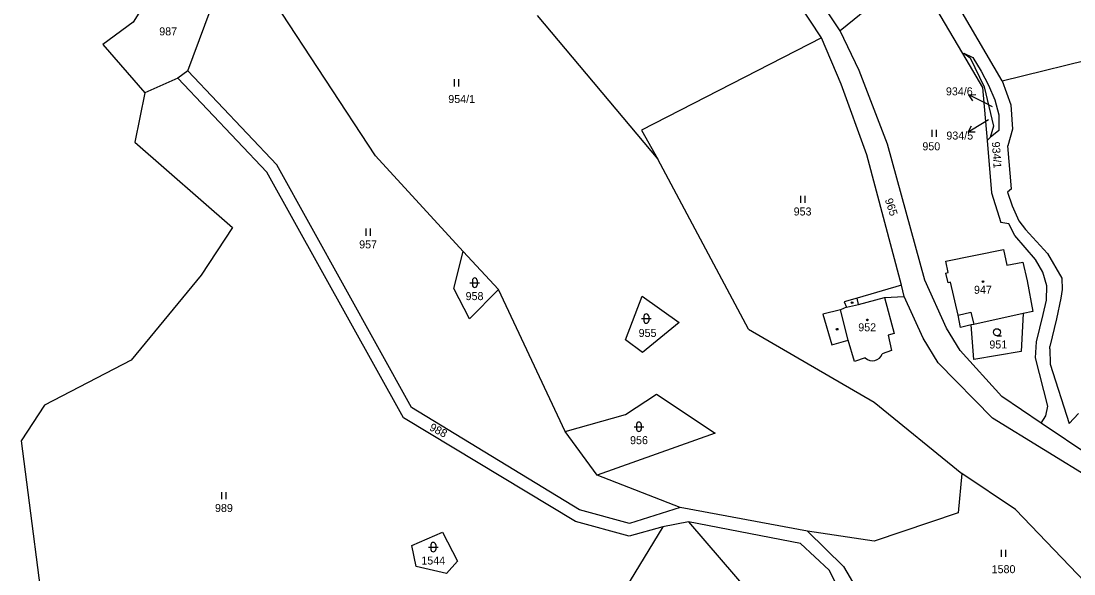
# Model space of a CAD drawing. Extents: x -670359 to -668019, y -978807 to -976674.
# Drawn here: x -669572.2 to -669348.5, y -977907.6 to -977790.2 of the extents above; entities that cross this region are included whole.
import ezdxf

# ---------------------------------------------------------------- set-up
doc = ezdxf.new("R2010")
doc.units = 0
for name, color, linetype in [('Hranice parcel', 7, 'Continuous'), ('Parcelní čísla', 7, 'Continuous'), ('Vnitřní kresba', 7, 'Continuous'), ('Značky budov', 7, 'Continuous'), ('Značky kultur', 7, 'Continuous')]:
    doc.layers.add(name, color=color, linetype=linetype)

msp = doc.modelspace()

# ---------------------------------------------------------------- linework, layer by layer
at = {"layer": 'Hranice parcel'}
for points in [[(-669496.86, -977818.78), (-669528.95, -977769.91)], [(-669398.16, -977792.22), (-669412.75, -977770.41)], [(-669402.15, -977793.77), (-669417.31, -977770.76)], [(-669363.72, -977802.89), (-669379.05, -977776.69)], [(-669540.35, -977777.57), (-669548.36, -977790.4)], [(-669382.48, -977779.5), (-669398.16, -977792.22)], [(-669382.48, -977779.5), (-669372.18, -977797.06)], [(-669536.76, -977800.75), (-669529.53, -977781.26)], [(-669548.36, -977790.4), (-669554.81, -977795.16)], [(-669462.55, -977789.01), (-669436.91, -977819.49)], [(-669394.12, -977800.67), (-669398.16, -977792.22)], [(-669554.81, -977795.16), (-669545.86, -977805.45)], [(-669402.15, -977793.77), (-669440.35, -977813.33)], [(-669397.94, -977803.57), (-669402.15, -977793.77)], [(-669372.18, -977797.06), (-669371.87, -977797.01)], [(-669372.18, -977797.06), (-669367.95, -977804.27)], [(-669371.87, -977797.01), (-669370.56, -977798)], [(-669371.87, -977797.01), (-669369.99, -977797.91)], [(-669370.56, -977798), (-669367.54, -977804.12)], [(-669369.99, -977797.91), (-669368.18, -977800.82)], [(-669536.76, -977800.75), (-669538.86, -977802.32)], [(-669517.84, -977820.71), (-669536.76, -977800.75)], [(-669388.11, -977816.3), (-669394.12, -977800.67)], [(-669368.18, -977800.82), (-669366.63, -977803.8)], [(-669538.86, -977802.32), (-669545.86, -977805.45)], [(-669519.94, -977822.28), (-669538.86, -977802.32)], [(-669392.5, -977818.56), (-669397.94, -977803.57)], [(-669367.54, -977804.12), (-669365.6, -977812.48)], [(-669366.63, -977803.8), (-669365.29, -977806.88)], [(-669363.72, -977802.89), (-669361.92, -977807.97)], [(-669545.86, -977805.45), (-669547.97, -977815.9)], [(-669367.95, -977804.27), (-669366.96, -977815.51)], [(-669365.29, -977806.88), (-669364.43, -977810.08)], [(-669361.92, -977807.97), (-669361.56, -977813.16)], [(-669364.43, -977810.08), (-669364.43, -977813.41)], [(-669365.6, -977812.48), (-669366.28, -977814.88)], [(-669440.35, -977813.33), (-669436.91, -977819.49)], [(-669366.28, -977814.88), (-669366.96, -977815.51)], [(-669364.43, -977813.41), (-669366.28, -977814.88)], [(-669361.56, -977813.16), (-669362.54, -977816.65)], [(-669547.97, -977815.9), (-669527.27, -977834.04)], [(-669380.2, -977845.18), (-669388.11, -977816.3)], [(-669366.96, -977815.51), (-669365.99, -977826.63)], [(-669361.75, -977825.81), (-669362.54, -977816.65)], [(-669478.28, -977839.13), (-669496.86, -977818.78)], [(-669417.65, -977855.63), (-669436.91, -977819.49)], [(-669385.15, -977846.25), (-669392.5, -977818.56)], [(-669489.25, -977872.21), (-669517.84, -977820.71)], [(-669490.95, -977874.43), (-669519.94, -977822.28)], [(-669361.75, -977825.81), (-669362.63, -977826.48)], [(-669362.63, -977826.48), (-669361.65, -977829.42)], [(-669365.99, -977826.63), (-669364.06, -977832.93)], [(-669361.65, -977829.42), (-669360.19, -977832.63)], [(-669362.31, -977833.23), (-669364.06, -977832.93)], [(-669361.02, -977835.69), (-669362.31, -977833.23)], [(-669360.19, -977832.63), (-669358.81, -977834.45)], [(-669527.27, -977834.04), (-669533.94, -977844.13)], [(-669358.81, -977834.45), (-669354.11, -977839.55)], [(-669356.64, -977840.83), (-669361.02, -977835.69)], [(-669480.23, -977846.97), (-669478.28, -977839.13)], [(-669470.72, -977847.16), (-669478.28, -977839.13)], [(-669373.12, -977852.63), (-669374.71, -977845.65), (-669375.18, -977845.76), (-669375.68, -977843.68), (-669375.18, -977843.57), (-669375.73, -977841.18), (-669363.45, -977838.66), (-669362.78, -977842.01), (-669359.38, -977841.34)], [(-669354.11, -977839.55), (-669351.08, -977844.76)], [(-669359.38, -977841.34), (-669358.45, -977845.37)], [(-669355.13, -977843.5), (-669356.64, -977840.83)], [(-669533.94, -977844.13), (-669548.78, -977862.2)], [(-669354.22, -977846.4), (-669355.13, -977843.5)], [(-669385.15, -977846.25), (-669394.58, -977849.02)], [(-669384.58, -977848.64), (-669385.15, -977846.25)], [(-669375.59, -977855.38), (-669380.2, -977845.18)], [(-669358.45, -977845.37), (-669357.26, -977851.85)], [(-669354.33, -977849.44), (-669354.22, -977846.4)], [(-669351.08, -977844.76), (-669351.03, -977847.19)], [(-669476.92, -977853.43), (-669480.23, -977846.97)], [(-669470.72, -977847.16), (-669476.92, -977853.43)], [(-669456.56, -977877.36), (-669470.72, -977847.16)], [(-669443.79, -977857.86), (-669440.24, -977848.57)], [(-669440.24, -977848.57), (-669432.37, -977854.2)], [(-669388.74, -977848.91), (-669384.58, -977848.64)], [(-669388.74, -977848.91), (-669386.7, -977856.49)], [(-669380.53, -977857.49), (-669384.58, -977848.64)], [(-669351.03, -977847.19), (-669351.29, -977849.05)], [(-669396.8, -977850.95), (-669398.08, -977851.52)], [(-669394.58, -977849.02), (-669397.29, -977849.76)], [(-669397.29, -977849.76), (-669396.8, -977850.95)], [(-669355, -977852.45), (-669354.33, -977849.44)], [(-669351.29, -977849.05), (-669352.17, -977853.37)], [(-669398.08, -977851.52), (-669401.83, -977852.42)], [(-669401.83, -977852.42), (-669399.96, -977858.96)], [(-669372.6, -977855.26), (-669373.12, -977852.63)], [(-669359.3, -977852.3), (-669369.79, -977854.59)], [(-669359.3, -977852.3), (-669359.73, -977860.32)], [(-669357.26, -977851.85), (-669359.3, -977852.3)], [(-669356.46, -977858.3), (-669355, -977852.45)], [(-669352.17, -977853.37), (-669353.65, -977859.3)], [(-669432.37, -977854.2), (-669440.18, -977860.56)], [(-669417.65, -977855.63), (-669390.94, -977871.13)], [(-669372.68, -977860.16), (-669375.59, -977855.38)], [(-669370.31, -977854.71), (-669372.6, -977855.26)], [(-669369.79, -977854.59), (-669370.31, -977854.71)], [(-669369.79, -977862.06), (-669370.31, -977854.71)], [(-669440.18, -977860.56), (-669443.79, -977857.86)], [(-669386.7, -977856.49), (-669387.98, -977856.89)], [(-669387.98, -977856.89), (-669387.24, -977860.16)], [(-669377.31, -977862.74), (-669380.53, -977857.49)], [(-669399.96, -977858.96), (-669396.45, -977857.9)], [(-669395.14, -977862.45), (-669396.45, -977857.9)], [(-669356.68, -977861.66), (-669356.46, -977858.3)], [(-669353.65, -977859.8), (-669353.65, -977859.3)], [(-669353.65, -977859.8), (-669353.58, -977863.01)], [(-669548.78, -977862.2), (-669567.21, -977871.76)], [(-669392.83, -977861.72), (-669395.14, -977862.45)], [(-669387.24, -977860.16), (-669389.23, -977860.82)], [(-669363.83, -977869.93), (-669372.68, -977860.16)], [(-669359.73, -977860.32), (-669369.79, -977862.06)], [(-669354.06, -977871.95), (-669356.68, -977861.66)], [(-669365.81, -977874.5), (-669377.31, -977862.74)], [(-669353.58, -977863.01), (-669349.49, -977875.6)], [(-669443.78, -977873.69), (-669437.17, -977869.41)], [(-669437.17, -977869.41), (-669424.73, -977877.65)], [(-669390.94, -977871.13), (-669372.28, -977886.27)], [(-669355.46, -977875.53), (-669363.83, -977869.93)], [(-669567.21, -977871.76), (-669572.17, -977879.31)], [(-669453.53, -977893.95), (-669489.25, -977872.21)], [(-669354.44, -977874.02), (-669354.06, -977871.95)], [(-669349.49, -977875.6), (-669347.5, -977873.51)], [(-669454.36, -977896.42), (-669490.95, -977874.43)], [(-669456.56, -977877.36), (-669443.78, -977873.69)], [(-669344.14, -977887.8), (-669365.81, -977874.5)], [(-669355.46, -977875.53), (-669354.44, -977874.02)], [(-669344.89, -977882.61), (-669355.46, -977875.53)], [(-669449.79, -977886.59), (-669456.56, -977877.36)], [(-669424.73, -977877.65), (-669449.79, -977886.59)], [(-669572.17, -977879.31), (-669566.4, -977923.76)], [(-669432.16, -977893.46), (-669449.79, -977886.59)], [(-669372.28, -977886.27), (-669373.09, -977894.58)], [(-669360.92, -977893.91), (-669372.28, -977886.27)], [(-669432.16, -977893.46), (-669442.92, -977896.86)], [(-669405.07, -977898.47), (-669432.16, -977893.46)], [(-669442.92, -977896.86), (-669453.53, -977893.95)], [(-669373.09, -977894.58), (-669390.93, -977900.62)], [(-669360.92, -977893.91), (-669341.2, -977914.44)], [(-669442.95, -977899.58), (-669454.36, -977896.42)], [(-669435.8, -977897.58), (-669451.69, -977923.64)], [(-669435.8, -977897.58), (-669442.95, -977899.58)], [(-669430.35, -977896.52), (-669435.8, -977897.58)], [(-669406.62, -977901.09), (-669430.35, -977896.52)], [(-669430.35, -977896.52), (-669416.9, -977912.18)], [(-669489.16, -977901.56), (-669482.64, -977898.67)], [(-669482.64, -977898.67), (-669479.42, -977904.86)], [(-669390.93, -977900.62), (-669405.07, -977898.47)], [(-669405.07, -977898.47), (-669397.47, -977905.99)], [(-669488.24, -977905.97), (-669489.16, -977901.56)], [(-669400.52, -977906.76), (-669406.62, -977901.09)], [(-669479.42, -977904.86), (-669481.77, -977907.48)], [(-669481.77, -977907.48), (-669488.24, -977905.97)], [(-669394.16, -977918.98), (-669400.52, -977906.76)], [(-669397.47, -977905.99), (-669391.02, -977916.94)]]:
    msp.add_lwpolyline(points, dxfattribs=at)
msp.add_arc((-669391.32, -977860.12), 2.2, 226.5107, 341.5618, dxfattribs=at)
at = {"layer": 'Parcelní čísla'}
for p, q in [((-669370.01, -977807.09), (-669370.83, -977805.84)), ((-669365.77, -977808.39), (-669367.26, -977807.64)), ((-669366.64, -977811.15), (-669367.56, -977811.71)), ((-669369.48, -977813.75), (-669370.98, -977813.78))]:
    msp.add_line(p, q, dxfattribs=at)
for points in [[(-669367.26, -977807.64), (-669370.83, -977805.84), (-669369.33, -977805.75)], [(-669367.56, -977811.71), (-669370.98, -977813.78), (-669370.26, -977812.46)]]:
    msp.add_lwpolyline(points, dxfattribs=at)
at = {"layer": 'Vnitřní kresba'}
for points in [[(-669363.72, -977802.89), (-669341.3, -977797.34)], [(-669394.25, -977850.38), (-669388.74, -977848.91)], [(-669396.8, -977850.95), (-669394.25, -977850.38)], [(-669394.25, -977850.38), (-669394.58, -977849.02)], [(-669396.45, -977857.9), (-669398.08, -977851.52)], [(-669373.12, -977852.63), (-669370.39, -977852), (-669369.79, -977854.59)]]:
    msp.add_lwpolyline(points, dxfattribs=at)
at = {"layer": 'Značky budov'}
for centre in [(-669367.8, -977845.48), (-669392.37, -977853.62)]:
    msp.add_circle(centre, 0.175, dxfattribs=at)
at = {"layer": 'Značky kultur'}
for p, q in [((-669480.15, -977802.55), (-669480.15, -977804.05)), ((-669479.15, -977804.05), (-669479.15, -977802.55)), ((-669378.67, -977813.29), (-669378.67, -977814.79)), ((-669377.67, -977814.79), (-669377.67, -977813.29)), ((-669406.61, -977827.26), (-669406.61, -977828.76)), ((-669405.61, -977828.76), (-669405.61, -977827.26)), ((-669498.91, -977834.25), (-669498.91, -977835.75)), ((-669497.91, -977835.75), (-669497.91, -977834.25)), ((-669476.8, -977845.73), (-669474.8, -977845.73)), ((-669476.3, -977845.23), (-669476.3, -977846.23)), ((-669475.3, -977845.23), (-669475.3, -977846.23)), ((-669440.34, -977853.36), (-669438.34, -977853.36)), ((-669439.84, -977852.86), (-669439.84, -977853.86)), ((-669438.84, -977852.86), (-669438.84, -977853.86)), ((-669364.85, -977857), (-669363.85, -977857)), ((-669441.9, -977876.32), (-669439.9, -977876.32)), ((-669441.4, -977875.82), (-669441.4, -977876.82)), ((-669440.4, -977875.82), (-669440.4, -977876.82)), ((-669529.58, -977890.22), (-669529.58, -977891.72)), ((-669528.58, -977891.72), (-669528.58, -977890.22)), ((-669485.59, -977901.87), (-669483.59, -977901.87)), ((-669485.09, -977901.37), (-669485.09, -977902.37)), ((-669484.09, -977901.37), (-669484.09, -977902.37)), ((-669363.98, -977902.43), (-669363.98, -977903.93)), ((-669362.98, -977903.93), (-669362.98, -977902.43))]:
    msp.add_line(p, q, dxfattribs=at)
for centre, radius in [((-669367.8, -977845.48), 0.175), ((-669395.62, -977849.97), 0.175), ((-669398.8, -977855.61), 0.175), ((-669392.37, -977853.62), 0.175), ((-669364.85, -977856.25), 0.75)]:
    msp.add_circle(centre, radius, dxfattribs=at)
for centre, start, end in [((-669475.8, -977845.23), 0, 180), ((-669475.8, -977846.23), 180, 0), ((-669439.34, -977852.86), 0, 180), ((-669439.34, -977853.86), 180, 0), ((-669440.9, -977875.82), 0, 180), ((-669440.9, -977876.82), 180, 0), ((-669484.59, -977901.37), 0, 180), ((-669484.59, -977902.37), 180, 0)]:
    msp.add_arc(centre, 0.5, start, end, dxfattribs=at)

# ---------------------------------------------------------------- texts
at = {"layer": 'Parcelní čísla'}
for s, height, p in [('987', 1.7, (-669542.81, -977793.22)), ('934/6', 1.7, (-669375.69, -977805.95)), ('954/1', 1.7, (-669481.41, -977807.58)), ('934/6', 0.1, (-669365.97, -977808.39)), ('934/5', 0.1, (-669366.84, -977811.15)), ('934/5', 1.7, (-669375.6, -977815.34)), ('950', 1.7, (-669380.69, -977817.62)), ('953', 1.7, (-669408.04, -977831.46)), ('957', 1.7, (-669500.34, -977838.45)), ('947', 1.7, (-669369.73, -977848.08)), ('958', 1.7, (-669477.73, -977849.43)), ('955', 1.7, (-669440.97, -977857.25)), ('952', 1.7, (-669394.31, -977856.05)), ('951', 1.7, (-669366.46, -977859.7)), ('956', 1.7, (-669442.79, -977880.02)), ('989', 1.7, (-669530.97, -977894.42)), ('1544', 1.7, (-669487.13, -977905.57)), ('1580', 1.7, (-669365.98, -977907.41))]:
    msp.add_text(s, height=height, dxfattribs=at).set_placement(p)
for s, rotation, p in [('934/1', 274.103, (-669365.95, -977815.85)), ('965', 288.3976, (-669388.69, -977828.13)), ('988', 332.6082, (-669485.58, -977876.96))]:
    msp.add_text(s, height=1.7, rotation=rotation, dxfattribs=at).set_placement(p)

doc.saveas('drawing.dxf')
